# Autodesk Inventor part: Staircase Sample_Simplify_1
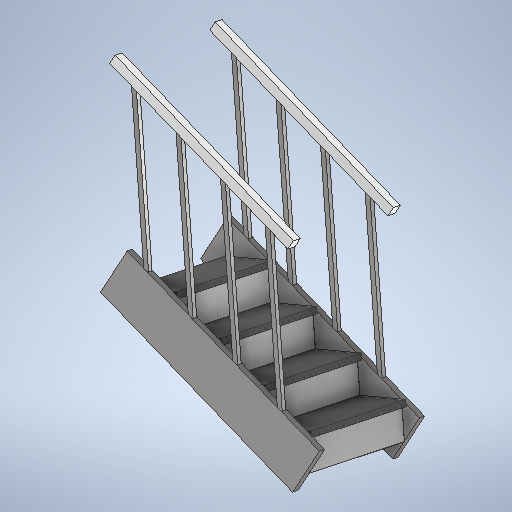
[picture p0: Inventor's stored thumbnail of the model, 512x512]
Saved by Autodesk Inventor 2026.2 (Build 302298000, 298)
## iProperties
Created: 2026-01
Part Number: Staircase Sample_Simplify_1
Material: Generic
Document SubType Name: Modeling
Designer: MichelleRasmussen
Density: 1 g/cm^3
Appearance: Default
Author: MichelleRasmussen
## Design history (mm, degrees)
derived "Staircase Sample.iam"
body "Solid1"
node "Stringer.ipt:1"
node "Tread.ipt:1"
body "Solid2"
node "Riser.ipt:1"
body "Solid3"
node "Baluster.ipt:1"
body "Solid4"
node "Railing.ipt:1"
body "Solid5"
node "Railing.ipt:4"
body "Solid6"
node "Left Stringer_MIR.ipt:1"
body "Solid7"
node "Baluster.ipt:7"
body "Solid8"
node "Tread.ipt:2"
body "Solid9"
node "Riser.ipt:2"
body "Solid10"
node "Baluster.ipt:8"
body "Solid11"
node "Baluster.ipt:12"
body "Solid12"
node "Tread.ipt:3"
body "Solid13"
node "Riser.ipt:3"
body "Solid14"
node "Baluster.ipt:13"
body "Solid15"
node "Baluster.ipt:15"
body "Solid16"
node "Tread.ipt:4"
body "Solid17"
node "Riser.ipt:4"
body "Solid18"
node "Baluster.ipt:16"
body "Solid19"
node "Baluster.ipt:17"
body "Solid20"
